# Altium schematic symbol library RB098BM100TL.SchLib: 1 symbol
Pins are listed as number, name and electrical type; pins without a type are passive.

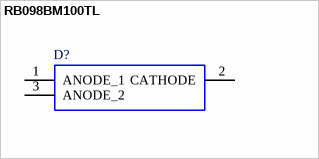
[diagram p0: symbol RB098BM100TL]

## RB098BM100TL
designator D?
Super Low IR, 100V, 6A, TO-252 (DPAK), Schottky Barrier Diode; Manufacturer_Name: ROHM Semiconductor
footprint RD3P175SNFRATL
pins: 1 ANODE_1, 2 CATHODE, 3 ANODE_2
